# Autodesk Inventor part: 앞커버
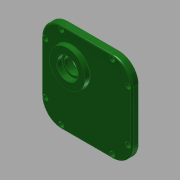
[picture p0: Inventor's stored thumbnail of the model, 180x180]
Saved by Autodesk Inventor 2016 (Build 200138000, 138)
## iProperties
Created: 2016-12
Part Number: 앞커버
Material: 일반
Document SubType Name: Modeling
Designer: mduedu
Density: 1 g/cm^3
Appearance: 매끄러움 - 짙은 산림 녹색
Mass: 191.493 g
Surface Area: 476.271 cm^2
Volume: 191.493 cm^3
Author: mduedu
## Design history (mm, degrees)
sketch "스케치1"
  geometry: L1 (-46, 42)-(-46, -36); L2 (-16, 72)-(62, 72); L3 (92, 42)-(92, -36); L4 (62, -66)-(-16, -66); A1 r 30 centre (-16, -36) between (-46, -36) and (-16, -66); A2 r 30 centre (62, 42) between (92, 42) and (62, 72); A3 r 30 centre (62, -36) between (62, -66) and (92, -36); A4 r 30 centre (-16, 42) between (-16, 72) and (-46, 42); 1 further point
  constraints: 8 end point, 8 point on circle, 8 tangent, 4 centre point, 3 equal radius, 2 perpendicular, 1 horizontal
  dimensions: "d89" = 30 radius of A2; "d90" = 92 distance from line of L3 point (0, 0); "d91" = 138 distance between parallel lines of L4 L2; "d92" = 72 distance from line of point (0, 0) L2; "d114" = 46 distance from line of point (0, 0) L1
extrude "돌출1" new body sketch "스케치1" distance "d3" = 10; taper "d4" = 0 deg
sketch "스케치2"
  geometry: C1 r 21 at (0, 26); 1 further point
  constraints: 1 centre point, 1 vertical alignment
  dimensions: "d5" = 42 diameter of C1; "d7" = 26 distance of C1.centre point (0, 0)
extrude "돌출2" join sketch "스케치2" distance "d8" = 7; taper "d9" = 0 deg
sketch "스케치3"
  geometry: C1 r 15 at (0, -28.87); C2 r 21 at (0, 26) reference; C3 r 15 at (-54.87, 26); 1 further point
  constraints: 2 centre point, 1 horizontal alignment, 1 vertical alignment
  dimensions: "d10" = 30 diameter of C1; "d71" = 54.87 distance of C1.centre C2.centre; "d94" = 30 diameter of C3; "d95" = 54.87 distance of C2.centre C3.centre
extrude "돌출3" join sketch "스케치3" distance "d12" = 7; taper "d13" = 0 deg; dims "d50" = 90 deg
sketch "스케치4"
  geometry: C1 r 21 at (0, 26) reference; C2 r 28 at (0, 26); 1 further point
  constraints: 1 centre point, 1 coincident
  dimensions: "d14" = 56 diameter of C2
extrude "돌출4" join sketch "스케치4" distance "d15" = 7; taper "d16" = -5 deg
hole "구멍1" diameter "d19" = 35; stored, may be unused: countersink angle "d23" = 90 deg, drill point angle "d25" = 0 deg; dims "d17" = 10, "d18" = 10, "d20" = 6, "d21" = 4, "d22" = 2, "d24" = 10
hole "구멍2" diameter "d28" = 22; stored, may be unused: countersink angle "d32" = 90 deg, drill point angle "d34" = 0 deg; dims "d26" = 10, "d27" = 10, "d29" = 6, "d30" = 4, "d31" = 2, "d33" = 7
hole "구멍8" diameter "d98" = 22; stored, may be unused: countersink angle "d102" = 90 deg, drill point angle "d104" = 0 deg; dims "d96" = 10, "d97" = 10, "d99" = 6, "d100" = 4, "d101" = 2, "d103" = 7
hole "구멍3" diameter "d37" = 19; stored, may be unused: countersink angle "d41" = 90 deg, drill point angle "d43" = 0 deg; dims "d35" = 10, "d36" = 10, "d38" = 6, "d39" = 4, "d40" = 2, "d42" = 1
hole "구멍9" diameter "d107" = 19; stored, may be unused: countersink angle "d111" = 90 deg, drill point angle "d113" = 0 deg; dims "d105" = 10, "d106" = 10, "d108" = 6, "d109" = 4, "d110" = 2, "d112" = 1
hole "구멍4" diameter "d46" = 32; stored, may be unused: countersink angle "d50" = 90 deg, drill point angle "d52" = 0 deg; dims "d44" = 10, "d45" = 10, "d47" = 6, "d48" = 4, "d49" = 2, "d51" = 8
hole "구멍5" diameter "d55" = 25; stored, may be unused: countersink angle "d59" = 90 deg, drill point angle "d61" = 0 deg; dims "d53" = 10, "d54" = 10, "d56" = 6, "d57" = 4, "d58" = 2, "d60" = 8
fillet "모깎기1" dims "d62" = 0.3
fillet "모깎기2" dims "d63" = 2
chamfer "모따기1" distance "d64" = 1; stored, may be unused: second distance "d65" = 2, angle "d66" = 45 deg
fillet "모깎기4" dims "d68" = 2
fillet "모깎기5" dims "d69" = 0.3
fillet "모깎기6" dims "d70" = 2
sketch "스케치5"
  geometry: L1 (62, 72)-(-16, 72) reference; L2 (92, -36)-(92, 42) reference; L3 (-16, -66)-(62, -66) reference; L4 (-46, 42)-(-46, -36) reference; L5 (-40, 42)-(-40, -36); L6 (-16, -60)-(62, -60); L7 (86, -36)-(86, 42); L8 (62, 66)-(-16, 66); A1 r 30 centre (62, 42) between (92, 42) and (62, 72) reference; A2 r 30 centre (62, -36) between (62, -66) and (92, -36) reference; A3 r 30 centre (-16, -36) between (-46, -36) and (-16, -66) reference; A4 r 30 centre (-16, 42) between (-16, 72) and (-46, 42) reference; A5 r 24 centre (-16, -36) between (-40, -36) and (-16, -60); A6 r 24 centre (62, -36) between (62, -60) and (86, -36); A7 r 24 centre (62, 42) between (86, 42) and (62, 66); A8 r 24 centre (-16, 42) between (-16, 66) and (-40, 42)
  constraints: 8 end point, 8 point on circle, 4 centre point, 7 other
  dimensions: "d93" = 6 distance between parallel lines of L5 L4
sketch "스케치7"
  geometry: L1 (62, 66)-(-16, 66) reference; L2 (86, -36)-(86, 42) reference; L3 (-16, -60)-(62, -60) reference; L4 (-40, 42)-(-40, -36) reference; A1 r 24 centre (62, 42) between (86, 42) and (62, 66) reference; A2 r 24 centre (62, -36) between (62, -60) and (86, -36) reference; A3 r 24 centre (-16, -36) between (-40, -36) and (-16, -60) reference; A4 r 24 centre (-16, 42) between (-16, 66) and (-40, 42) reference; 8 further points
  constraints: 8 coincident
hole "구멍7" sketch "스케치7" at (-40, 42), (-40, -36), (-16, -60), (62, -60), (86, -36), (86, 42), (62, 66), (-16, 66) diameter "d80" = 4.5; stored, may be unused: countersink angle "d84" = 90 deg, drill point angle "d86" = 0 deg; dims "d81" = 6, "d82" = 8, "d83" = 4.6, "d85" = 8
node "솔리드1"
